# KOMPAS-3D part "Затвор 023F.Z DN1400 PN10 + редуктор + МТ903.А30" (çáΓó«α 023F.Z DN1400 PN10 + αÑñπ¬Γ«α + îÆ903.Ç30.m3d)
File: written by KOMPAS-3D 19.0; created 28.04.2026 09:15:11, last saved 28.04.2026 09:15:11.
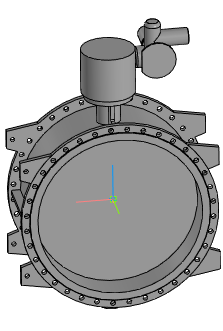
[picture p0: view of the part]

Document properties: Автор: Энергия; Полное имя файла: ..\..\Затвор 023F.Z DN400-DN1600 + редуктор + МТ903\Затвор 023F.Z DN1400 PN10 + редуктор + МТ903.А30.a3d

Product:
- Part/product: Затвор 023F.Z DN1400 PN10 + редуктор + МТ903.А30
    Масса: 3477.36

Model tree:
1. Операция без истории:1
